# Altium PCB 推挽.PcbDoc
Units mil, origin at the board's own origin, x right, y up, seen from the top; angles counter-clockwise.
Board outline 10000 x 8000 mil, 2 copper layers (Top Layer, Bottom Layer); 62 components, 72 nets, 189 pads, 6 vias.
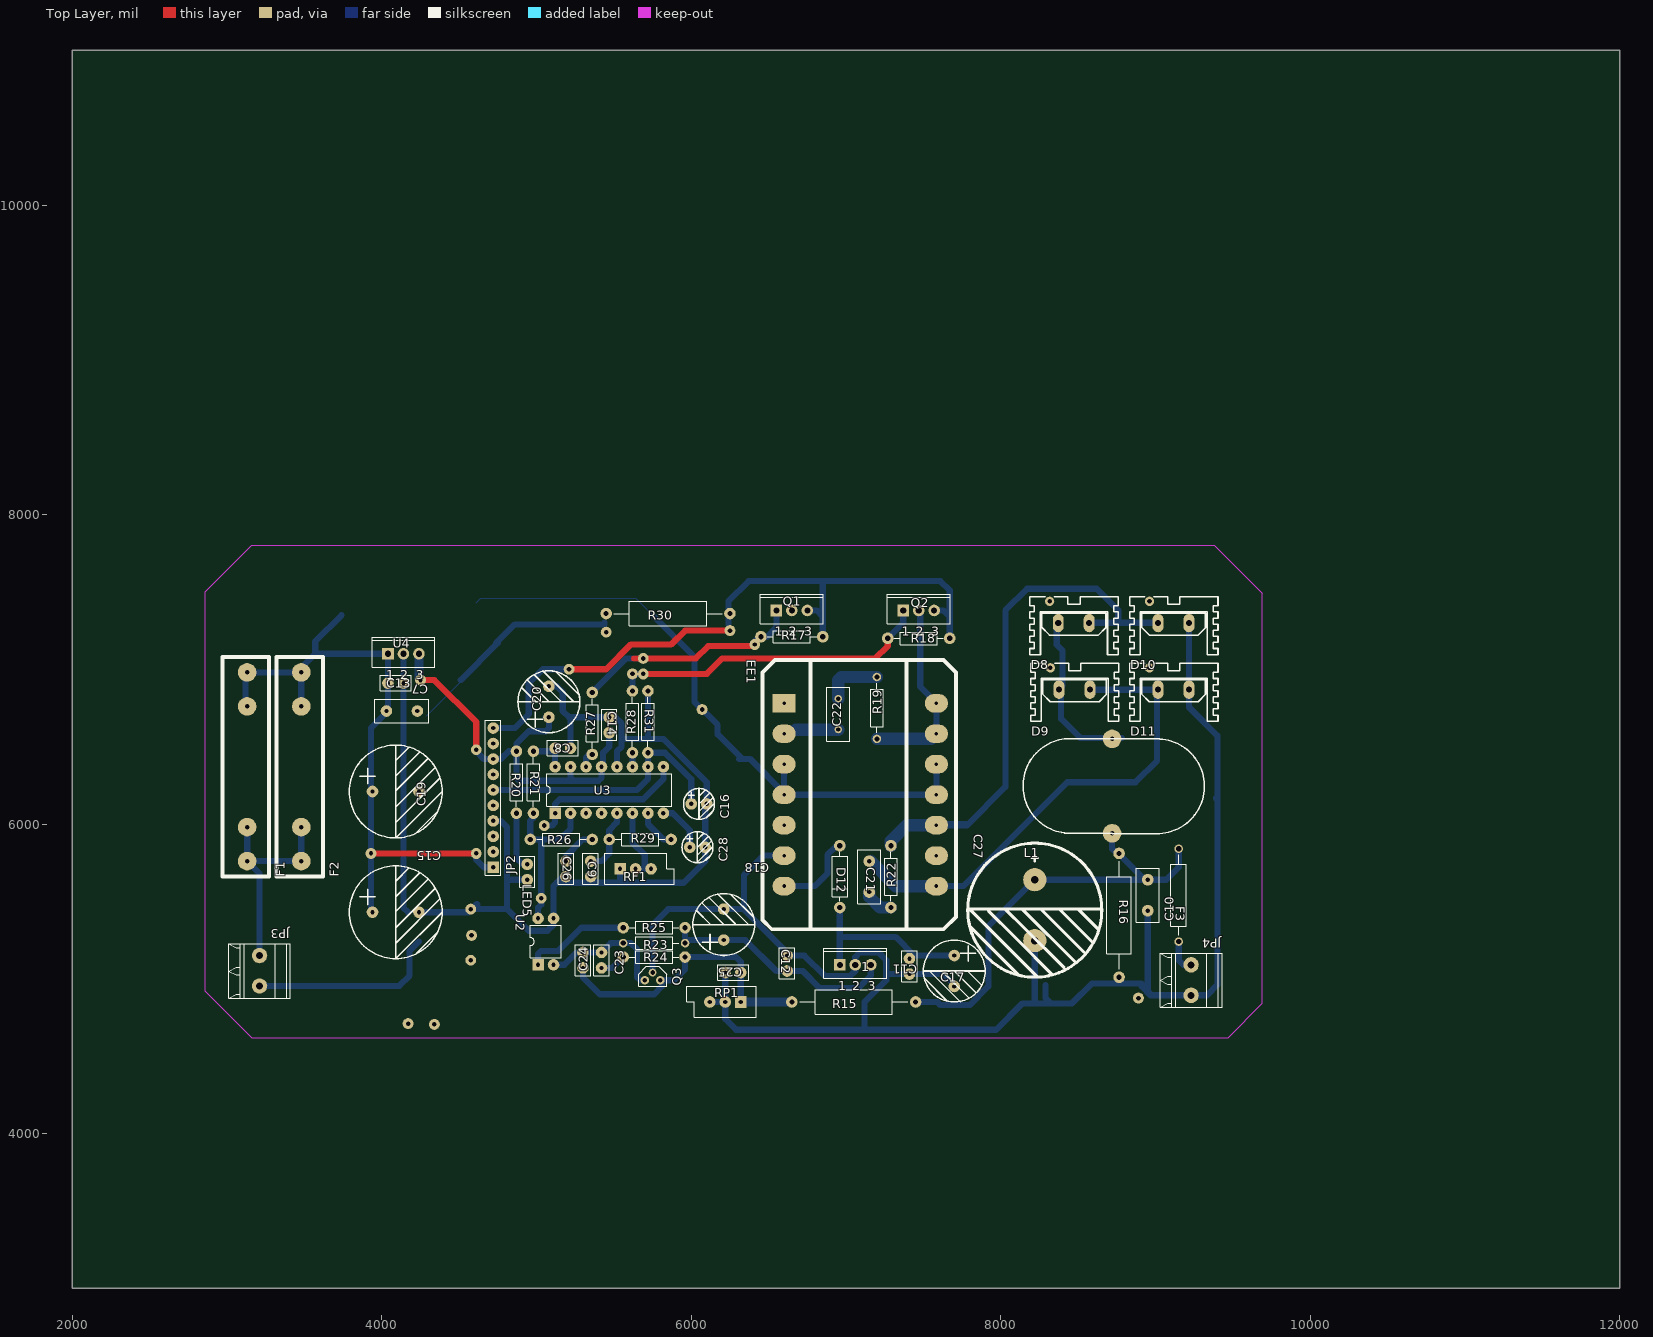
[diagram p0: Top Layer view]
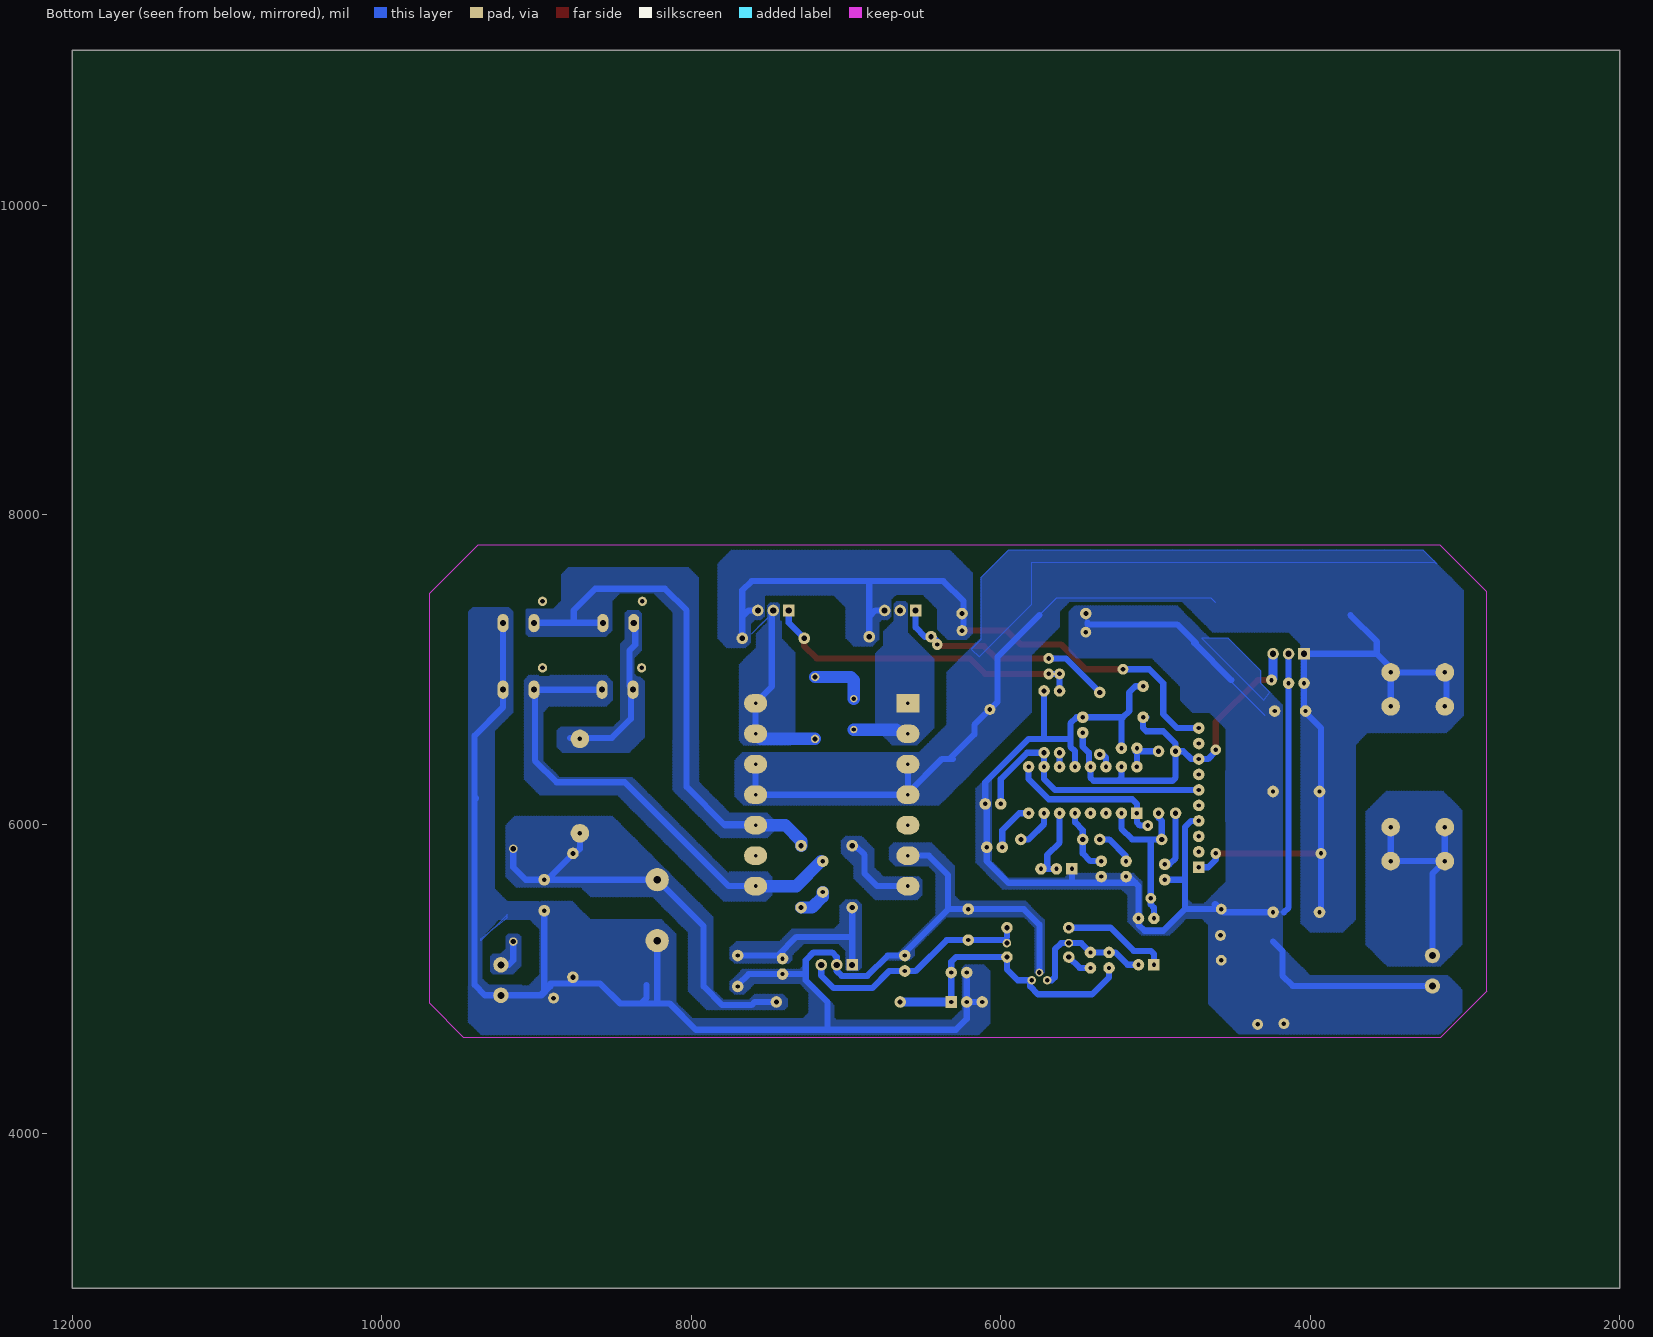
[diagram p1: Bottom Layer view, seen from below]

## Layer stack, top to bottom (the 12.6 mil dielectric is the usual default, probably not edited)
Top Layer: signal copper 1.4
Dielectric: dielectric 12.6, FR-4, Dk 4.8
Bottom Layer: signal copper 1.4

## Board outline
2000,3000 12000,3000 12000,11000 2000,11000

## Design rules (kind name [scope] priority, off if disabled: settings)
Clearance [All] p1: gap=8
ComponentClearance [All] p1: gap=10 collisioncheckmode=0
FanoutControl Fanout_BGA [IsBGA] p1: bgadir=Out bgaviamode=Centered fanoutstyle=Auto fanoutdirection=InThenOut viagrid=1 // Fanout_BGA (Default Rule)
FanoutControl Fanout_LCC [IsLCC] p2: bgadir=Out bgaviamode=Centered fanoutstyle=Auto fanoutdirection=InThenOut viagrid=1 // Fanout_LCC (Default Rule)
FanoutControl Fanout_SOIC [IsSOIC] p3: bgadir=Out bgaviamode=Centered fanoutstyle=Auto fanoutdirection=InThenOut viagrid=1 // Fanout_SOIC (Default Rule)
FanoutControl Fanout_Small [(CompPinCount < 5)] p4: bgadir=Out bgaviamode=Centered fanoutstyle=Auto fanoutdirection=InThenOut viagrid=1 // Fanout_Small (Default Rule)
FanoutControl Fanout_Default [All] p5: bgadir=Out bgaviamode=Centered fanoutstyle=Auto fanoutdirection=InThenOut viagrid=1 // Fanout_Default (Default Rule)
PlaneConnect [All] p1: planeconnectstyle=Direct reliefexpansion=20 reliefentries=4 reliefconductorwidth=10 reliefairgap=10
PolygonConnect [All] p1: connectstyle=Direct reliefconductorwidth=10 reliefentries=4 polygonreliefangle="90 Angle"
RoutingLayers [All] p1: top layer=Horizontal bottom layer=Vertical
RoutingVias [All] p1: holewidth=25 width=40 viastyle="Through Hole" minholewidth=28 minwidth=50 maxholewidth=28 maxwidth=50
SolderMaskExpansion [All] p1: expansion=4
TestPointUsage [All] p1: valid=0 allowmultiple=FALSE
Testpoint [All] p1: side=15 testpointundercomponent=TRUE minsize=40 maxsize=100 preferedsize=60 minholesize=0 maxholesize=40 preferedholesize=32 testpointgrid=1 style=1023 order=-539222988
Width [All] p1: maxlimit=50 minlimit=8 preferedwidth=40
10 further rules are at their usual default settings.

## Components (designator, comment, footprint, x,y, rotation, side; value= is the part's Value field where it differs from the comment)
1 "Volt Reg" SFM-T3/X1.6V 7060,5090 r0 top
C7 "Cap" RAD-0.2#1 4230,6730 r180 top (schematic designator C13)
C8 "Cap" RAD-0.1 5220,6490 r180 top (schematic designator C7)
C9 "Cap" RAD-0.1 5350,5760 r270 top (schematic designator C8)
C10 "Cap" RAD-0.2#1 8950,5440 r90 top (schematic designator C9)
C11 "Cap" RAD-0.1 7410,5030 r90 top
C12 "Cap" RAD-0.1 6620,5150 r270 top
C13 "Cap" RAD-0.1 4140,6910 r180 top (schematic designator C14)
C14 "Cap" RAD-0.1 5470,6690 r270 top (schematic designator C15)
C15 "Cap Pol1" RB.3/.6 4090,5430 r180 top (schematic designator C20)
C16 "Cap Pol1" rb.1/.2 6050,6130 r180 top (schematic designator C17)
C17 "Cap Pol1" RB.2/.4 7500,4850 r90 top (schematic designator C18)
C18 "Cap Pol1" RB.2/.4 6410,5550 r270 top (schematic designator C19)
C19 "Cap Pol1" RB.3/.6 4090,6210 r180 top (schematic designator C21)
C20 "Cap Pol1" RB.2/.4 5280,6990 r270 top (schematic designator C22)
C21 "222" RAD-0.2#1 7150,5560 r90 top (schematic designator C24)
C22 "222" RAD-0.2#2 6950,6610 r90 top
C23 "222" rad-0.1 5420,5070 r90 top (schematic designator C25)
C24 "222" rad-0.1 5300,5070 r90 top (schematic designator C26)
C25 "222" rad-0.1 6220,5040 r0 top (schematic designator C27)
C26 "103" RAD-0.1 5190,5760 r270 top (schematic designator C28)
C27 "68uF/450V" 100uF/450V 8220,5640 r270 top (schematic designator C29)
C28 "47uF" RB.1/.2 6040,5850 r180 top (schematic designator C30)
D8 "MUR860" RHRP8120 8185,7470 r0 top
D9 "MUR860" RHRP8120 8190,7040 r0 top
D10 "MUR860" RHRP8120 8830,7470 r0 top
D11 "MUR860" RHRP8120 8830,7040 r0 top
D12 "FR207" diode-0.4 6960,5660 r270 top
EE1 "" EE44 6600,6780 r0 top
F1 "10A" FUSE 3130,5760 r90 top
F2 "10A" FUSE 3480,5760 r90 top
F3 "10A" axial-0.6 9150,5540 r270 top
JP2 "Header 10" HDR1X10 4720,5720 r90 top
JP3 "24V电源输入" JK128-500-2P 3210,5150 r270 top (schematic designator JP4)
JP4 "12V电源输入" JK128-500-2P 9230,5090 r270 top (schematic designator JP3)
L1 "1.5mH" 1mH 8720,5940 r90 top
LED5 "LED0" RAD-0.1 4940,5740 r270 top (schematic designator LED3)
Q1 "75NF75" SFM-T3/X1.6V 6650,7380 r0 top
Q2 "75NF75" SFM-T3/X1.6V 7470,7380 r0 top
Q3 "TL431" TO-92A 5800,4990 r180 top
R15 "Res2" AXIAL-0.8 7050,4850 r0 top (schematic designator R14)
R16 "Res2" AXIAL-0.8 8765,5410 r90 top (schematic designator R15)
R17 "Res2" AXIAL-0.4#1 6650,7210 r180 top (schematic designator R16)
R18 "Res2" AXIAL-0.4#1 7470,7200 r180 top (schematic designator R17)
R19 "Res2" AXIAL-0.4#2 7200,6750 r90 top (schematic designator R18)
R20 "Res2" AXIAL-0.4#1 4870,6270 r270 top (schematic designator R19)
R21 "1.2K" AXIAL-0.4#1 4980,6270 r270 top (schematic designator R20)
R22 "1.2K" AXIAL-0.4#1 7290,5660 r90 top (schematic designator R21)
R23 "360" AXIAL-0.4#2 5760,5230 r0 top
R24 "360" AXIAL-0.4#1 5760,5140 r0 top (schematic designator R22)
R25 "470" AXIAL-0.4#1 5760,5330 r0 top (schematic designator R23)
R26 "150k" AXIAL-0.4#1 5160,5900 r0 top (schematic designator R24)
R27 "" AXIAL-0.4#1 5360,6650 r90 top (schematic designator R25)
R28 "" AXIAL-0.4#1 5620,6660 r90 top (schematic designator R26)
R29 "" AXIAL-0.4#1 5670,5900 r0 top (schematic designator R27)
R30 "康铜电阻" AXIAL-0.8 5850,7360 r0 top (schematic designator R28)
R31 "10K" AXIAL-0.4#1 5720,6660 r270 top (schematic designator R29)
RF1 "RPot2" VR5 5640,5710 r0 top (schematic designator RF2)
RP1 "RPot2" VR5 6220,4850 r180 top
U2 "PC817B" DIP-4 5060,5240 r0 top
U3 "KA3525A" dip-16 5470,6220 r0 top
U4 "7812" SFM-T3/X1.6V 4140,7100 r0 top

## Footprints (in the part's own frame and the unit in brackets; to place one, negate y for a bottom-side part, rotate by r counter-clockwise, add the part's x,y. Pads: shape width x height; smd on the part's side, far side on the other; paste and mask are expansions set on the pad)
1mH [mil]
  round 120 hole 28: 1(0,0) 2(610,0)
  silkscreen extent -2,-596 612,576
100uF/450V [mm]
  round 3.81 hole 1.27: 1(0,0) 2(10,0)
  silkscreen extent -6,-11 16,11
AXIAL-0.4#1 [mm]
  round 1.905 hole 0.85: 1(-5.08,0) 2(5.08,0)
  silkscreen extent -4.06,-1.02 4.06,1.02
AXIAL-0.4#2 [mm]
  round 1.4 hole 0.85: 1(-5.08,0) 2(5.08,0)
  silkscreen extent -4.06,-1.02 4.06,1.02
axial-0.6 [mm]
  round 1.4 hole 0.85: 1(-7.62,0) 2(7.62,0)
  silkscreen extent -6.6,-1.27 6.6,1.27
AXIAL-0.8 [mm]
  round 1.905 hole 0.85: 1(-10.16,0) 2(10.16,0)
  silkscreen extent -8.89,-2.03 8.89,2.03
diode-0.4 [mm]
  round 1.905 hole 0.85: 1(-5.08,0) 2(5.08,0)
  silkscreen extent -4.06,-1.27 4.06,1.27
DIP-4 [mil]
  rect 75x75 hole 28: 1(-50,-150)
  round 75 hole 28: 2(50,-150) 3(50,150) 4(-50,150)
  silkscreen extent -100,-104 100,104
dip-16 [mil]
  rect 75x75 hole 28: 1(-350,-150)
  round 75 hole 28: 2(-250,-150) 3(-150,-150) 4(-50,-150) 5(50,-150) 6(150,-150) 7(250,-150) 8(350,-150) 9(350,150) 10(250,150) 11(150,150) 12(50,150) 13(-50,150) 14(-150,150) 15(-250,150) 16(-350,150)
  silkscreen extent -406,-104 406,104
EE44 [mm]
  rect 3.81x3.048 hole 0.6: 1(0,0)
  oval 3.81x3.048 hole 0.6: 2(0,-5) 3(0,-10) 4(0,-15) 5(0,-20) 6(0,-25) 7(0,-30) 8(25,-30) 9(25,-25) 10(25,-20) 11(25,-15) 12(25,-10) 13(25,-5) 14(25,0)
  silkscreen extent -3.56,-37.08 28.19,7.11
FUSE [mil]
  round 120 hole 30: 1(0,0) 1(220,0) 2(1000,0) 2(1220,0)
  silkscreen extent -100,-140 1320,160
HDR1X10 [mil]
  rect 75x75 hole 28: 1(0,0)
  round 75 hole 28: 2(100,0) 3(200,0) 4(300,0) 5(400,0) 6(500,0) 7(600,0) 8(700,0) 9(800,0) 10(900,0)
  silkscreen extent -50,-50 950,50
JK128-500-2P [mil]
  round 100 hole 45: 1(0,0) 2(196.85,0)
  silkscreen extent -75,-200 275,200
RAD-0.1 [mm]
  round 1.905 hole 0.7: 1(0,0) 2(2.54,0)
  silkscreen extent -1.27,-1.27 3.81,1.27
rad-0.1 [mm]
  round 1.905 hole 0.7: 1(0,0) 2(2.54,0)
  silkscreen extent -1.27,-1.27 3.81,1.27
RAD-0.2#1 [mm]
  round 1.905 hole 0.7: 1(0,0) 2(5.08,0)
  silkscreen extent -1.91,-1.91 6.98,1.91
RAD-0.2#2 [mm]
  round 1.2 hole 0.7: 1(0,0) 2(5.08,0)
  silkscreen extent -1.91,-1.91 6.98,1.91
rb.1/.2 [mil]
  round 75 hole 28: 1(50,0) 2(-50,0)
  silkscreen extent -100,-100 100,100
RB.1/.2 [mil]
  round 75 hole 28: 1(50,0) 2(-50,0)
  silkscreen extent -100,-100 100,100
RB.2/.4 [mil]
  round 75 hole 28: 1(300,-200) 2(100,-200)
  silkscreen extent 0,-400 400,0
RB.3/.6 [mil]
  round 75 hole 28: 1(150,0) 2(-150,0)
  silkscreen extent -300,-300 300,300
RHRP8120 [mm]
  oval 1.8x3 hole 1: 1(9.819,-4.366) 2(4.739,-4.366)
  round 1.524 hole 0.762: ""(3.328,-0.784)
  silkscreen extent 0.08,-9.53 14.58,-0.03
SFM-T3/X1.6V [mm]
  rect 1.905x1.905 hole 1: 1(-2.54,0)
  round 1.905 hole 1: 2(0,0) 3(2.54,0)
  silkscreen extent -5.15,-2.2 5.15,2.7
TO-92A [mil]
  round 55 hole 30: 1(0,0) 3(100,0)
  round 50 hole 30: 2(50,-50)
  silkscreen extent -40,-90 140,40
VR5 [mm]
  rect 1.905x1.905 hole 0.7: 1(-2.54,0)
  round 1.905 hole 0.7: 2(0,0) 3(2.54,0)
  silkscreen extent -5.08,-2.54 6.35,2.54

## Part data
1: "Voltage Regulator"
C7 C8 C9 C10 C11 C12 C13 C14: "Capacitor"
C15 C16 C17 C18 C19 C20: "Polarized Capacitor (Radial)"
C21 C22 C23 C24 C25 C26: library part CAP, "Capacitor"
C27: library part 22UF/35V_E, "CCER1-226S035"
C28: library part 4.7UF/400V_E, "CCER2-475S400"
D8 D9 D10 D11 D12: library part Diode, "Default Diode"
EE1: library part EE44
F1 F2 F3: library part "Fuse 1", "Fuse"
JP2: "Header, 10-Pin"
JP3 JP4: library part "Header 2", "Header, 2-Pin"
L1: library part 6.8UH, "CL-NLFC3225-6R8"
LED5: "Typical INFRARED GaAs LED"
Q1 Q2: library part IRF840, "CQ-IRF840"
R15 R16 R17 R18 R19 R20: "Resistor"
R21 R22 R23 R24 R25 R26 R27 R28 R29 R31: library part 1.1K, "CR85-112J"
R30: library part Res2, "Resistor"
RF1 RP1: "Potentiometer"
U2: library part PC817C
U4: library part LM7812

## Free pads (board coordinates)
  round 70 hole 30: 0(5210,7000) 0(6070,6740) 1(5450,7240) 1(6250,7250) 2(4575,5450) 3(4580,5280) 4(4575,5120) 5(4340,4705) 6(4170,4710) 7(8890,4875) 8(5690,7070) 9(5620,6970) 10(5030,5520) 11(5050,5990)

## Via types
v1: diameter 70, hole 28, Top Layer to Bottom Layer, 6 vias

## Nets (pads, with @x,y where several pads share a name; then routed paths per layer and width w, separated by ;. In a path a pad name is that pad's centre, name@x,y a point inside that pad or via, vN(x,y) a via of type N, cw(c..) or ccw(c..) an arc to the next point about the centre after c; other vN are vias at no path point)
15V: 1.3 C12.2 C18.1 R23.2 R25.2 | length 1511.5
  Bottom Layer w40: R23.2 5960,5250 6350,5250 6550,5050 6720,5050 6830,4940 7080,4940 7160,5020 1.3 ; 5960,5270 R25.2
GND: C7.1 C8.1 C9.2 C13.1 C14.1 C15.2 C16.2 C19.2 C20.2 C26.2 C28.2 JP2.4 JP3.2 LED5.2 pad.1@5450,7240 pad.2 pad.3 pad.4 pad.5 pad.6 R30.1 R31.1 RF1.1 U2.3 U3.12 U4.2 | length 10225.7
  Bottom Layer w8: 4170,5430 C15.2 ; 4290,6700 4510,6920 4510,6930
  Bottom Layer w40: JP3.2 4113.15,4953.15 4180,5020 4180,5180 4240,5240 ; U4.2 C13.1 4140,5460 4170,5430 ; C15.2@4230,5430 pad.2@4560,5430 ; 4510,6930 4750,7170 ; pad.2 4810,5450 ; pad.2@4577.5,5447.5 4613.24,5483.24 4616.48,5480 ; JP2.4 4770,6020 4810,5980 4810,5450 ; 4740,7170 4860,7290 5440,7290 5440,7300 ; 4810,5640 LED5.2 ; C20.2 5130,6890 5170,6850 5170,6730 5210,6690 C14.1 ; U2.3@5100,5380 U2.3@5110,5370 ; 5110,5350 5070,5310 4950,5310 4810,5450 ; U2.3 5110,5600 5170,5660 C26.2 ; 5130,5620 5950,5620 6090,5760 6090,6120 C16.2 6100,6270 5820,6550 5550,6550 ; C8.1 5220,6690 ; 5350,5620 C9.2 ; 5510,6690 5550,6650 5550,6500 5520,6470 U3.12 ; 5540,5620 RF1.1 ; 5720,6560 R31.1
Net1_1: 1.1 C11.2 C17.1 D12.2 | length 1218
  Bottom Layer w40: 1.1 6960,5440 D12.2@6980,5460 ; 6960,5270 7320,5270 7440,5150 C17.1 ; C11.2 7410,5180
NetC1_2: 
NetC2_1: 
NetC3_2: 
NetC4_1: 
NetC8_2: C8.2 R21.1 U3.16 | length 254.1
  Bottom Layer w40: R21.1 5130,6470 5120,6460 U3.16
NetC9_1: C9.1 R29.1 U3.5 | length 421.4
  Bottom Layer w40: C9.1 5420,5760 5470,5810 5470,5960 5520,6010 U3.5
NetC10_2: C10.2 C27.1 F3.1 L1.1 R15.2 R16.2 | length 2818.2
  Bottom Layer w40: R15.2 7590,4850 7610,4830 7800,4830 7920,4950 7920,5340 C27.1 9070,5640 9150,5720 F3.1 ; L1.1 8720,5840 8750,5810 8760,5810 C10.2@8930,5640
NetC11_2: 
NetC12_1: 
NetC12_2: 
NetC13_1: 
NetC13_2: 
NetC14_1: 
NetC14_2: 
NetC15_1: 
NetC16_1: C16.1 JP2.6 R31.2 U3.10 | length 1709.4
  Bottom Layer w40: JP2.6 5650,6220 5720,6290 R31.2 5830,6460 6000,6290 C16.1
NetC19_1: 
NetC20_1: 
NetC21_1: C21.1 R22.1 | length 199
  Bottom Layer w80: C21.1 7150,5530 7220,5460 R22.1
NetC21_2: C21.2 D9.1 D11.2 EE1.8 | length 3173.5
  Bottom Layer w40: C21.2@7140,5760 C21.2@7160,5760 ; EE1.8@7598.9,5598.9 7600,5600 7760,5600 8430,6270 8870,6270 9010,6410 D11.2@9010,6868.12 ; D9.1@8570,6870 D9.1@8571.88,6868.12 ; D9.1 D11.2
  Bottom Layer w80: C21.2@7160,5760 7321.1,5598.9 EE1.8@7598.9,5598.9
NetC22_1: C22.1 EE1.1 EE1.2 Q1.2 | length 275.1
  Bottom Layer w80: 6674.85,6610 C22.1
NetC22_2: C22.2 R19.2 | length 378.3
  Bottom Layer w80: C22.2 6950,6930 6970,6950 R19.2
NetC23_1:  | length 38
  Bottom Layer w40: 6600,6583.15 6626.85,6610
NetC23_2: C23.2 C24.2 Q3.3 R23.1 U2.2 | length 852.8
  Bottom Layer w40: U2.2 5180,5090 5260,5170 C23.2 5480,5230 5610,5230 5650,5190 5650,5010 5670,4990 Q3.3
NetC24_1: C24.1 C25.2 Q3.1 R15.1 R24.2 RP1.1 | length 1897.7
  Bottom Layer w40: C24.1 5300,5010 5410,4900 5760,4900 5810,4950 Q3.1@5810,4990 ; Q3.1 5890,4990 5960,5060 R24.2@5960,5130 ; R24.2 6290,5140 6320,5110 RP1.1
  Bottom Layer w60: RP1.1 R15.1
NetC24_1: C23.1 R24.1 | length 169
  Bottom Layer w40: C23.1 5490,5070 R24.1
NetC26_1: C26.1 R26.2 | length 245.6
  Bottom Layer w40: C26.1 5190,5790 5300,5900 R26.2
NetC28_1: C28.1 U3.8 | length 325.6
  Bottom Layer w40: U3.8 5880,6070 5990,5960 C28.1
NetC28_2: 
NetD1_1: 
NetD1_2: 
NetD2_1: 
NetD5_1: 
NetD6_1: 
NetD8_1: D8.1 D10.2 EE1.10 R22.2 | length 3634.6
  Bottom Layer w40: 7790,6000 7590,6000 7600,5990 7780,5990 8030,6240 8030,7380 8170,7520 8620,7520 8760,7380 8760,7300 ; D8.1@8570,7310 8560,7300 D10.2@9000,7300
  Bottom Layer w80: R22.2 7290,5890 7392.6,5992.6 EE1.10
NetD8_2: 
NetD8_2: D8.2 D9.2 L1.2 | length 1082.8
  Bottom Layer w40: D8.2@8361.57,7298.12 8361.57,7158.43 8400,7120 8400,6891.55 8390,6881.55 8390,6680 8513.48,6556.52 8783.48,6556.52
NetD9_2: 
NetD12_1: D12.1 EE1.7 | length 558.4
  Bottom Layer w40: EE1.7 6798.9,5598.9 6880,5680 6880,5800 6940,5860 D12.1@6980,5860
NetD12_2: 
NetDS1_1: 
NetDS2_1: 
NetEE1_13: EE1.13 EE1.14 Q2.2 R19.1 | length 1242.2
  Bottom Layer w40: Q2.2 7480,7370 7480,6888.5 7584.25,6784.25 EE1.13 EE1.13@7551.1,6550
  Bottom Layer w80: R19.1 EE1.13@7551.1,6550
NetF1_1: F1.1 F2.1 JP3.1 | length 1403.1
  Bottom Layer w40: F1.1@3130,5770 F1.1@3130,5980 ; JP3.1 3210,5680 3130,5760 F2.1@3460,5760 ; F2.1@3480,5760 F2.1@3480,5980
NetF3_2: F3.2 JP4.1 | length 226.6
  Bottom Layer w40: F3.2 9150,5120 9180,5090 JP4.1 JP4.1@9240,5080
NetJP2_10: JP2.10 pad.0@5210,7000 pad.1@6250,7250 Q1.3 Q2.3 R17.1 R18.1 R30.2 | length 4459.9
  Top Layer w40: pad.0@5210,7000 5450,7000 5610,7160 5870,7160 5960,7250 pad.1@6250,7250
  Bottom Layer w40: JP2.10 4860,6620 4950,6710 4950,6910 5040,7000 pad.0@5210,7000 ; 6240,7290 6240,7440 6370,7570 7610,7570 7670,7510 R18.1 ; Q1.3 6810,7380 6850,7340 ; R17.1 6850,7560 ; Q2.3 7630,7380 7670,7340
NetLED1_1: 
NetLED2_1: 
NetLED5_1: LED5.1 R20.2 | length 380.7
  Bottom Layer w40: R20.2 4870,5780 4910,5740 4930,5740 LED5.1@4940,5730
NetQ1_1: pad.8 Q1.1 R17.2 R27.2 | length 1555.7
  Top Layer w40: 5630,7070 6030,7070 6110,7150 6400,7150 v1(6410,7160)
  Bottom Layer w40: R27.2 5580,7070 pad.8 ; v1@6410,7150 6410,7180 6440,7210 6490,7210 6550,7270 Q1.1
NetQ2_1: pad.9 Q2.1 R18.2 R28.2 | length 2116
  Top Layer w40: v1(5690,6970) 6100,6970 6200,7070 7190,7070 7270,7150 R18.2@7270,7210
  Bottom Layer w40: R28.2 pad.9 v1(5690,6970) ; R18.2 7370,7300 Q2.1
NetR1_2: 
NetR14_2: 
NetR17_2: 
NetR21_2: pad.10 R21.2 R26.1 U2.4 U3.2 | length 1065.6
  Bottom Layer w40: 4960,6010 R26.1 5150,5900 5220,5970 5220,5990 ; 4960,6020 4980,6040 R21.2 ; U2.4 5010,5460 5030,5480 5030,5900 ; 5220,6000 U3.2
NetR22_1: 
NetR25_1: R25.1 U2.1 | length 690.4
  Bottom Layer w40: U2.1 5010,5160 5030,5180 5140,5180 5290,5330 R25.1
NetR25_1: 
NetR26_2: 
NetR27_1: R27.1 U3.14 | length 108.3
  Bottom Layer w40: U3.14 5320,6430 5340,6450 R27.1
NetR28_1: R28.1 U3.11 | length 90
  Bottom Layer w40: U3.11 R28.1
NetR29_2: R29.2 U3.7 | length 261.4
  Bottom Layer w40: U3.7 5720,6000 5820,5900 R29.2
NetRF1_2: RF1.2 RF1.3 U3.6 | length 497.3
  Bottom Layer w40: U3.6 5620,5880 5700,5800 5700,5720 RF1.3@5710,5710 ; RF1.2@5650,5710 RF1.3@5750,5710
NetRF1_2: 
NetU2_1: 
NetU3_1: pad.11 U3.1 U3.9 | length 1044.6
  Bottom Layer w40: pad.11 5100,5990 5120,6010 5120,6130 5150,6160 5690,6160 5820,6290 U3.9
SGND: 1.2 C10.1 C11.1 C12.1 C17.2 C18.2 C25.1 C27.2 D10.1 D11.1 EE1.6 JP4.2 pad.7 Q3.2 R16.1 RP1.2 RP1.3 | length 10982.8
  Bottom Layer w40: Q3.2 5750,5350 5850,5450 6340,5450 ; RP1.3 RP1.2 ; C25.1 6220,4740 6290,4670 7970,4670 8140,4840 8460,4840 8590,4970 8910,4970 ; EE1.6 6465.75,5795.75 6340,5670 6340,5450 ; C12.1 6730,5150 6862,5018 7028,5018 7060,5050 7060,5140 7090,5170 7210,5170 7260,5120 7260,4990 7120,4850 7120,4680 ; C12.1@6640,5150 6340,5450 ; 7260,5030 7630,5030 7700,4960 C17.2 ; 8210,4840 8220,4850 C27.2 ; 8290,4960 8290,4875 8310,4855 ; 8910,4960 8910,4950 8966.85,4893.15 9333.15,4893.15 9400,4960 9400,6570 9216.57,6753.43 D10.1 ; C10.1 8950,4920 8960,4910 ; D11.1@9216.57,6866.57 D11.1@9220,6870 ; 9391.02,6166.02 9395,6170
VCC+12V: C14.2 C20.1 JP2.8 R20.1 U3.13 U3.15 U4.3 | length 2670.2
  Top Layer w40: v1(4250,6930) 4340,6930 4610,6660 v1(4610,6480)
  Bottom Layer w8: v1@4240,6940 v1(4250,6930)
  Bottom Layer w40: v1(4610,6480) 4610,6470 4660,6420 4770,6420 4820,6470 R20.1 ; C20.1@5060,6690 C20.1 5080,6620 5060,6600 4950,6600 4870,6520 4870,6300 4890,6280 5400,6280 5420,6300 U3.13 ; U3.15 5220,6300 5240,6280 ; U3.13@5430,6370 5430,6460 5470,6500 C14.2
  Bottom Layer w60: v1@4240,6940 U4.3
VCC+24V: C7.2 C13.2 C15.1 C19.1 EE1.3 EE1.4 EE1.11 EE1.12 F1.2 F2.2 JP2.1 pad.0@6070,6740 U4.1 | length 8431.7
  Top Layer w40: v1(3930,5810) v1(4610,5810)
  Bottom Layer w8: 4610,7430 4640,7460 5640,7460 5750,7350
  Bottom Layer w40: F1.2@3120,6760 3120,6970 3130,6980 3480,6980 F2.2@3490,6970 ; F2.2@3480,6760 3480,6940 F2.2@3510,6970 ; F2.2@3490,6980 3490,7020 3570,7100 ; 3740,7350 3570,7180 3570,7100 ; C15.1 3930,5440 3930,6620 4040,6730 U4.1 3570,7100 ; v1(4610,5810) 4610,5770 4660,5720 JP2.1 ; 5750,7350 6020,7080 6020,6790 6170,6640 6170,6580 6320,6430 ; 6310,6420 6380,6420 EE1.4@6600,6200 ; EE1.3 EE1.4@6600,6200 ; EE1.12 EE1.11 6610.55,6189.45 EE1.4@6600,6200
pads on no net: D8. D9. D10. D11. EE1.5 EE1.9 JP2.2 JP2.3 JP2.5 JP2.7 JP2.9 U3.3 U3.4

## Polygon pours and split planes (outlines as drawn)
GND on Bottom Layer (hatched 90Degree grid 10 track 10, remove dead copper): 4660,5510 4690,5480 4760,5480 4780,5500 4800,5520 4820,5520 4820,5460 4950,5330 5070,5330 5080,5340 5090,5350 5090,5630 5140,5680 5560,5680 5570,5670 5590,5650 5950,5650 6060,5760 6060,6290 6100,6290 6120,6270 6140,6250 6160,6230 6160,5750 5990,5580 5220,5580 5180,5540 5180,5370 5090,5280 4910,5280 4900,5290 4800,5390 4700,5390 4655,5345
Net1_1 on Bottom Layer (hatched 90Degree grid 10 track 10, remove dead copper): 6930,5510 7000,5510 7040,5470 7040,5360 7080,5320 7350,5320 7430,5240 7710,5240 7740,5210 7750,5200 7750,5130 7730,5110 7720,5100 7370,5100 7350,5120 7350,5150 7300,5200 7270,5230 7050,5230 7020,5200 7000,5180 7000,5050 6920,5050 6900,5070 6900,5480
NetD12_1 on Bottom Layer (hatched 90Degree grid 10 track 10, remove dead copper): 6550,5660 6760,5660 6820,5720 6820,5840 6900,5920 7000,5920 7030,5890 7030,5810 6990,5770 6950,5730 6950,5650 6880,5580 6830,5530 6810,5510 6540,5510 6510,5540 6510,5640 6530,5660
SGND on Bottom Layer (hatched 90Degree grid 10 track 10, remove dead copper): 6550,5730 6680,5730 6720,5770 6720,5850 6700,5870 6690,5880 6450,5880 6300,5730 6300,5540 6270,5510 6260,5500 5840,5500 5720,5380 5720,5040 5740,5020 5760,5020 5770,5030 5780,5040 5780,5330 5850,5400 6350,5400 6560,5190 6560,5150 6590,5120 6750,5120 6710,5160 6670,5160 6420,5410 6420,5680 6470,5730
NetC21_2 on Bottom Layer (hatched 90Degree grid 10 track 10, remove dead copper): 7530,5690 7510,5690 7480,5660 7480,5540 7520,5500 7790,5500 8480,6190 8980,6190 9080,6290 9080,6930 9050,6960 8990,6960 8980,6950 8920,6950 8910,6960 8550,6960 8510,6920 8510,6800 8550,6760 8920,6760 8960,6720 8960,6410 8850,6300 8380,6300 7760,5680 7770,5690
NetD8_1 on Bottom Layer (hatched 90Degree grid 10 track 10, remove dead copper): 7540,6070 7510,6070 7470,6030 7470,5950 7510,5910 7810,5910 8120,6220 8120,6550 7951.46,6550 7951.46,6270 7751.46,6070
NetC10_2 on Bottom Layer (hatched 90Degree grid 10 track 10, remove dead copper): 8590,6050 9140,6050 9200,5990 9200,5660 9140,5600 9130,5590 8710,5590 8650,5530 8250,5530 8020,5300 8020,4920 7910,4810 7900,4800 7400,4800 7380,4820 7380,4870 7400,4890 7410,4900 7590,4900 7630,4860 7790,4860 7860,4930 7860,5400 8210,5750 8510,6050
SGND on Bottom Layer (hatched 90Degree grid 10 track 10, remove dead copper): 6220,4810 6230,4820 6250,4800 6330,4720 6210,4720
SGND on Bottom Layer (hatched 90Degree grid 10 track 10, remove dead copper): 6250,4990 6250,5070 6230,5090 6110,5090 6070,5050 6070,4760 6160,4760
SGND on Bottom Layer (hatched 90Degree grid 10 track 10, remove dead copper): 9094.52,4955 9050,4955 9010,4995 8980,5025 8980,5500 8770,5500 8650,5380 8190,5380 8100,5290 8100,4850 8000,4750 7990,4740 7280,4740 7240,4780 7240,4910 7300,4970 7590,4970 7640,4920 7650,4910 7660,4900 7720,4900 7750,4930 7750,4980 7720,5010 7680,5050 7670,5060 7300,5060 7270,5090 7260,5080 7260,5010 7080,4830 7080,4750 7060,4730 6280,4730 6250,4760 6250,5040 6220,5070 6190,5070 6160,5040 6160,4920 6140,4900 6090,4900 6070,4880 6070,4710 6150,4630 9350,4630 9440,4720 9440,4960
GND on Bottom Layer (hatched 90Degree grid 5 track 5, remove dead copper): 4560,6680 4560,6635 4545,6620 4545,5400 4430,5400 4430,6665
SGND on Bottom Layer (hatched 90Degree grid 5 track 5, remove dead copper): 9420,5530 9420,7360 9380,7400 9190,7400 9155,7365 9155,7285 9325,7285 9325,5540
SGND on Bottom Layer (hatched 90Degree grid 5 track 5, remove dead copper): 9190,5395 9190,5415 9360,5245 9360,5260
SGND on Bottom Layer (hatched 90Degree grid 5 track 5, remove dead copper): 9190,5395 9190,5415 9195,5410 9200,5405
NetD8_1 on Bottom Layer (hatched 90Degree grid 5 track 5, remove dead copper): 8815,7210 9050,7210 9070,7230 9070,7380 9060,7390 8890,7390 8840,7440 8840,7610 8790,7660 8715,7660
NetD8_1 on Bottom Layer (hatched 90Degree grid 5 track 5, remove dead copper): 7951.46,6531.46 7951.46,7590 8021.46,7660 8740,7660 8820,7580 8820,7210 8560,7210 8530,7240 8530,7420 8500,7450 8480,7470 8460,7490 8240,7490 8200,7450 8160,7410 8120,7370 8120,6470 8000,6350 8000,6495
NetJP2_10 on Bottom Layer (hatched 90Degree grid 5 track 5, remove dead copper): 6540,7490 6510,7490 6470,7450 6410,7390 6410,7260 6340,7190 6295,7190 6295,7360 6260,7360 6390,7490
VCC+24V on Bottom Layer (hatched 90Degree grid 5 track 5, remove dead copper): 5760,7130 5800,7090 5800,6720 6230,6290 6300,6290 6300,6340 5950,6690 5950,7150 5770,7150
VCC+24V on Bottom Layer (hatched 90Degree grid 5 track 5, remove dead copper): 5620,7600 5620,7270 5730,7160 5760,7130 5880,7130 5890,7140
VCC+24V on Bottom Layer (hatched 90Degree grid 5 track 5, remove dead copper): 5530,7460 5970,7020 5970,7290 5750,7510 5520,7510
VCC+24V on Bottom Layer (hatched 90Degree grid 5 track 5, remove dead copper): 5600,7460 5600,7400 5540,7460
VCC+24V on Bottom Layer (hatched 90Degree grid 5 track 5, remove dead copper): 6220,7110 6260,7070 6270,7060 6270,6530 6160,6530 6040,6650 6040,7110
NetC23_1 on Bottom Layer (hatched 90Degree grid 5 track 5, remove dead copper): 7505,7330 7510,7330 7560,7280 7590,7250 7610,7230 7600,7240
NetJP2_10 on Bottom Layer (hatched 90Degree grid 5 track 5, remove dead copper): 6180,7230 6220,7190 6320,7190 6360,7230 6380,7250 6380,7410 6450,7480 6800,7480 6800,7770 6330,7770 6210,7650 6180,7620
GND on Bottom Layer (hatched 90Degree grid 5 track 5, remove dead copper): 4200,4640 4460,4640 4660,4840 4660,5510 4570,5600 4440,5730 4440,5910 4520,5990 4550,6020 4550,6340 4460,6430 4270,6430 4270,6200 4230,6200 4230,5570 4400,5400 4400,4870 4180,4650
GND on Bottom Layer (hatched 90Degree grid 5 track 5, remove dead copper): 5005,7070 5510,7070 5550,7110 5560,7120 5560,7370 5520,7410 5480,7410 5480,7370 5470,7360 5470,7140 5040,7140
GND on Bottom Layer (hatched 90Degree grid 5 track 5, remove dead copper): 5080,7130 4840,6890 4840,6800 4760,6720 4650,6720 4580,6650 4485,6555 4400,6640 4310,6730 4230,6730 4280,6780 4540,6780 4780,7020 4910,7150
GND on Bottom Layer (hatched 90Degree grid 5 track 5, remove dead copper): 4470,5540 4490,5540 4490,6730 4340,6580 4340,5520 4250,5430
VCC+24V on Bottom Layer (hatched 90Degree grid 5 track 5, remove dead copper): 4010,7110 4170,7270 4050,7270 4010,7230
NetF1_1 on Bottom Layer (hatched 90Degree grid 10 track 10, remove dead copper): 3030,6100 3140,6210 3510,6210 3640,6080 3640,5220 3520,5100 3500,5080 3160,5080 3110,5130 3040,5200 3020,5220 3020,6090
VCC+24V on Bottom Layer (hatched 90Degree grid 10 track 10, remove dead copper): 3110,6600 3010,6700 3010,7410 3210,7610 4600,7610 4680,7530 4680,7290 4630,7240 3860,7240 3790,7170 3790,7030 3730,6970 3650,6890 3650,6730 3540,6620 3510,6590 3120,6590
GND on Bottom Layer (hatched 90Degree grid 10 track 10, remove dead copper): 4260,6850 4180,6770 4180,5200 4120,5140 4070,5090 4000,5020 3110,5020 3020,4930 3020,4740 3120,4640 4200,4640 4490,4930 4490,5540 4380,5650 4350,5680 4350,6850
GND on Bottom Layer (hatched 90Degree grid 10 track 10, remove dead copper): 4380,5620 4390,5610 4390,6650 4890,7150 5480,7150 5510,7180 5540,7210 5540,7370 5500,7410 4860,7410 4300,6850 4300,5680
VCC+24V on Bottom Layer (hatched 90Degree grid 10 track 10, remove dead copper): 4680,7290 4820,7430 4830,7440 5540,7440 5540,7670 5520,7690 3190,7690 3010,7510 3010,7380 3120,7380 3260,7520 3260,7600 4570,7600 4570,7300
VCC+24V on Bottom Layer (hatched 90Degree grid 10 track 10, remove dead copper): 5520,7690 5920,7690 6050,7560 6120,7490 6120,7210 6220,7110 6220,6650 6370,6500 6370,6350 6320,6300 6250,6300 5900,6650 5900,7160 5860,7200 5620,7440 5500,7440
VCC+24V on Bottom Layer (hatched 90Degree grid 10 track 10, remove dead copper): 3500,6590 3630,6590 3710,6510 3710,5380 3790,5300 4000,5300 4050,5350 4060,5360 4060,7330 3810,7330 3580,7100 3580,6740
GND on Bottom Layer (hatched 90Degree grid 10 track 10, remove dead copper): 4260,6850 4320,6910 4320,6990 4530,7200 4700,7200 4520,7020 4300,6800
GND on Bottom Layer (hatched 90Degree grid 10 track 10, remove dead copper): 4260,6850 4320,6910 4320,6990 4530,7200 4680,7200 4680,7170 4240,6730 4210,6730
GND on Bottom Layer (hatched 90Degree grid 10 track 10, remove dead copper): 4700,6980 4830,6980 4970,7120 5500,7120 5550,7170 5550,7370 5510,7410 5050,7410
GND on Bottom Layer (hatched 90Degree grid 10 track 10, remove dead copper): 4380,6590 4780,6990 4600,6990 4330,6720 4200,6720 4270,6650
VCC+24V on Bottom Layer (hatched 90Degree grid 10 track 10, remove dead copper): 3182.6,7682.6 3250,7750 3270,7770 5950,7770 6130,7590 6130,7190 6190,7130 6140,7080 6010,7210 5800,7420 5800,7690 3200,7690
VCC+24V on Bottom Layer (hatched 90Degree grid 10 track 10, remove dead copper): 3190,7690 3270,7770 5950,7770 6130,7590 6130,7140 6070,7200 6070,7530 5920,7680 3250,7680 3250,6920 3090,6920 3090,7560
NetF3_2 on Bottom Layer (hatched 90Degree grid 5 track 5, remove dead copper): 9140,5290 9120,5290 9100,5270 9100,5080 9150,5030 9280,5030 9300,5050 9300,5140 9280,5160 9230,5160 9200,5190 9200,5270 9190,5280 9180,5290
SGND on Bottom Layer (hatched 90Degree grid 5 track 5, remove dead copper): 9095,4960 9310,4960 9350,5000 9350,5270 9300,5320 9270,5350 9270,6600 9170,6700 9160,6710 9150,6720 9150,7370 9180,7400 9335,7400 9335,5560 9420,5560 9420,4840 9385,4805 9080,4805
SGND on Bottom Layer (hatched 90Degree grid 5 track 5, remove dead copper): 9426.91,4836.91 9440,4850 9440,7370 9410,7400 9200,7400 9200,7295 9420,7295 9420,4840
SGND on Bottom Layer (hatched 90Degree grid 5 track 5, remove dead copper): 8920,5495 8980,5495 8985,5500 9190,5500 9290,5600 9290,5335 9275,5350 9245,5380 9040,5380 8970,5310 8925,5355
NetD8_2 on Bottom Layer (hatched 90Degree grid 5 track 5, remove dead copper): 8340,7380 8410,7380 8430,7360 8430,7190 8460,7160 8460,6670 8520,6610 8830,6610 8870,6570 8870,6500 8830,6460 8400,6460 8300,6560 8300,6920 8330,6950 8350,6950 8360,6960 8370,6970 8370,7070 8330,7110 8320,7120 8320,7360
NetD8_2 on Bottom Layer (hatched 90Degree grid 5 track 5, remove dead copper): 8870,6560 8870,6600 8850,6620 8840,6630 8485,6630 8545,6570
NetD8_1 on Bottom Layer (hatched 90Degree grid 5 track 5, remove dead copper): 8510,7440 8510,7250 8550,7210 8640,7210 8640,7350
NetJP2_10 on Bottom Layer (hatched 90Degree grid 10 track 10, remove dead copper): 6795,7480 7520,7480 7530,7470 7530,7340 7550,7320 7590,7320 7620,7290 7620,7170 7650,7140 7770,7140 7830,7200 7830,7680 7750,7760 7740,7770 6770,7770
NetJP2_10 on Bottom Layer (hatched 90Degree grid 10 track 10, remove dead copper): 6680,7480 6700,7460 6710,7450 6710,7340 6730,7320 6770,7320 6790,7300 6790,7190 6830,7150 6950,7150 7000,7200 7000,7400 7110,7510
NetEE1_13 on Bottom Layer (hatched 90Degree grid 10 track 10, remove dead copper): 7460,7430 7490,7430 7500,7420 7510,7410 7510,7300 7550,7260 7580,7230 7580,7140 7630,7090 7690,7030 7690,6540 7660,6510 7360,6510 7330,6540 7330,7110 7400,7180 7420,7200 7420,7310 7430,7320 7430,7420 7440,7430
VCC+24V on Bottom Layer (hatched 90Degree grid 10 track 10, remove dead copper): 6370,6500 6400,6470 6410,6460 7670,6460 7700,6430 7720,6410 7720,6180 7670,6130 7660,6120 6400,6120 6190,6330
VCC+24V on Bottom Layer (hatched 90Degree grid 10 track 10, remove dead copper): 6265,7065 6340,6990 6350,6980 6350,6640 6580,6410 6660,6330 6520,6330 6420,6430 6235,6615 6235,6950
NetC22_1 on Bottom Layer (hatched 90Degree grid 5 track 5, remove dead copper): 6630,7440 6670,7440 6690,7420 6690,7310 6720,7280 6740,7260 6760,7240 6760,6570 6700,6510 6540,6510 6470,6580 6430,6620 6430,7010 6560,7140 6590,7170 6600,7180 6600,7420 6620,7440
NetC22_1 on Bottom Layer (hatched 90Degree grid 5 track 5, remove dead copper): 6605,7380 6605,7240 6430,7065 6430,6990 6635,7195 6635,7405
NetC22_1 on Bottom Layer (hatched 90Degree grid 5 track 5, remove dead copper): 6750,7160 6790,7120 6810,7100 6810,6650 6740,6580

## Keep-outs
Keep-Out Layer:
  lines w8: 2860,7450 2860,7500 3160,7800 9380,7800 9690,7490 9690,4840 9470,4620 3160,4620 2860,4920 2860,7460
